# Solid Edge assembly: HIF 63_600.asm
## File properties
Title: Zylinder
Author: ahadarics
Template: iso assembly.asm
Last saved by: ahadarics
Revision: 58
Application: Solid Edge
Username: ahadarics
Dokumentum tartalom típus: 1
Document Number: HIF 63/600
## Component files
Kit_2.par
Kit_1.par
Profilrohr 63_600.par
Kolbenstange 63_600.par
Mutter.par
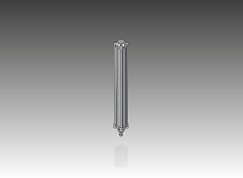
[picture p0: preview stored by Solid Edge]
